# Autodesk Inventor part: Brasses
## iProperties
Shininess: 77.0
Length Units: 11269
Angle Units: 11279
Time Units: 11290
Mass Units: 11283
Length Display Precision: 3
Angle Display Precision: 2
Created: 2002-02
Part Number: Brasses
Document SubType Name: Modeling
Designer: ***
Density: 0.0
Volumn: 0.0
Area: 0.0
PropertySet Name: Model Information
Control State: 0
Master: False
Checked Out: False
Author: ***
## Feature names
1. Revolution1
2. Hole1
3. Extrusion1
4. Hole2
